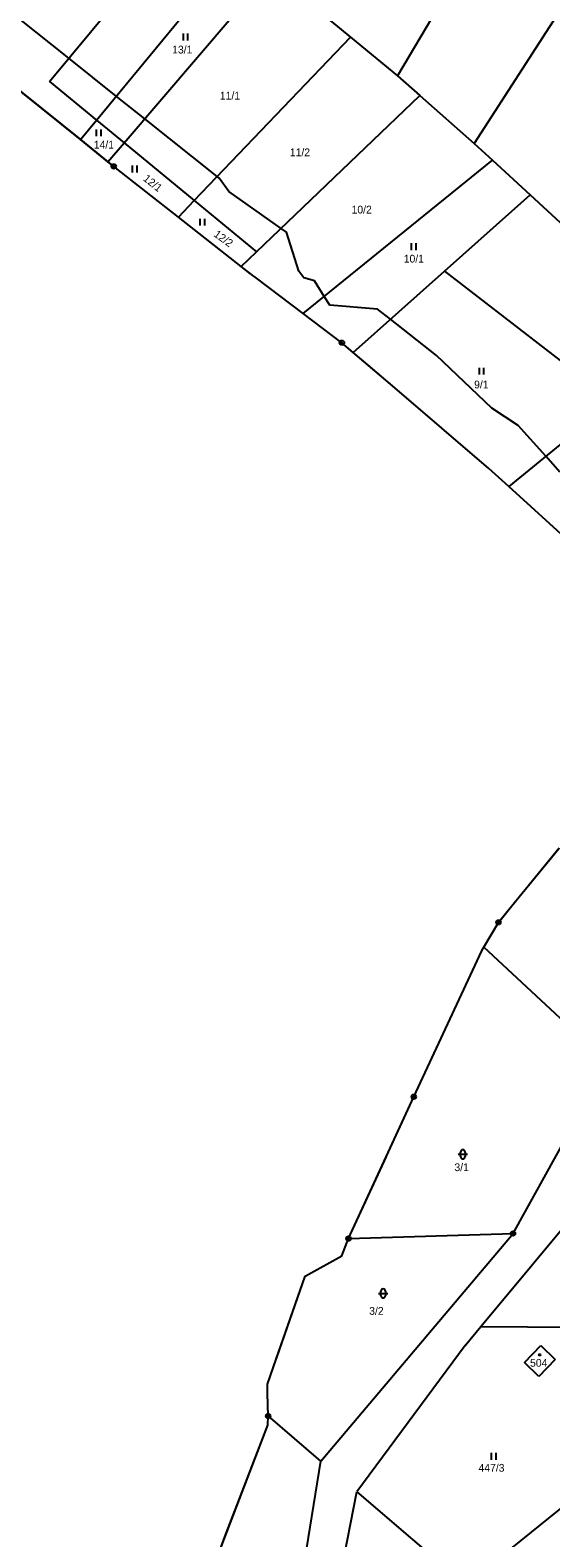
# Model space of a CAD drawing. Extents: x -445050 to -440454, y -1134563 to -1129741.
# Drawn here: x -443020.5 to -442906.4, y -1131200.4 to -1130870 of the extents above; entities that cross this region are included whole.
import ezdxf

# ---------------------------------------------------------------- set-up
doc = ezdxf.new("R2010")
doc.units = 0
for name, color, linetype in [('Vrstva 1', 7, 'Continuous'), ('Vrstva 13', 7, 'Continuous'), ('Vrstva 18', 7, 'Continuous'), ('Vrstva 19', 7, 'Continuous'), ('Vrstva 24', 7, 'Continuous'), ('Vrstva 25', 7, 'Continuous'), ('Vrstva 3', 7, 'Continuous'), ('Vrstva 37', 7, 'Continuous'), ('Vrstva 52', 7, 'Continuous')]:
    doc.layers.add(name, color=color, linetype=linetype)

msp = doc.modelspace()

# ---------------------------------------------------------------- linework, layer by layer
at = {"layer": 'Vrstva 1'}
for p, q in [((-442921.71, -1131154.07), (-442895.21, -1131122.14)), ((-442950.71, -1131134.82), (-442914.67, -1131133.71)), ((-442925.19, -1131158.26), (-442921.71, -1131154.07)), ((-442921.71, -1131154.07), (-442901.29, -1131154.25))]:
    msp.add_line(p, q, dxfattribs=at)
for points in [[(-442886.95, -1130790.6), (-442940, -1130880.07)], [(-442864.79, -1130804.31), (-442923.19, -1130894.89)], [(-443016.25, -1130881.25), (-442984.58, -1130843.19)], [(-443005.94, -1130889.74), (-442974.45, -1130851.57)], [(-442999.88, -1130894.74), (-442967.75, -1130857.11)], [(-442962.01, -1130861.86), (-442950.31, -1130871.54)], [(-442984.54, -1130907.39), (-442950.31, -1130871.54)], [(-442950.31, -1130871.54), (-442940, -1130880.07)], [(-443016.25, -1130881.25), (-443005.94, -1130889.74)], [(-442940, -1130880.07), (-442935.12, -1130884.38)], [(-442970.89, -1130918.64), (-442935.12, -1130884.38)], [(-442935.12, -1130884.38), (-442923.19, -1130894.89)], [(-443009.46, -1130894.01), (-443005.94, -1130889.74)], [(-443005.94, -1130889.74), (-442999.88, -1130894.74)], [(-443003.41, -1130898.87), (-442999.88, -1130894.74)], [(-442999.88, -1130894.74), (-442984.54, -1130907.39)], [(-442923.19, -1130894.89), (-442919.18, -1130898.55)], [(-442960.65, -1130932.13), (-442919.18, -1130898.55)], [(-442919.18, -1130898.55), (-442910.91, -1130906.11)], [(-442988, -1130911.01), (-442984.54, -1130907.39)], [(-442984.54, -1130907.39), (-442970.89, -1130918.64)], [(-442929.68, -1130922.83), (-442910.91, -1130906.11)], [(-442910.91, -1130906.11), (-442904.31, -1130912.16)], [(-442974.22, -1130921.83), (-442970.89, -1130918.64)], [(-442949.68, -1130940.64), (-442929.68, -1130922.83)], [(-442929.68, -1130922.83), (-442892.79, -1130951.31)], [(-442903.63, -1130960.22), (-442915.59, -1130970.05)], [(-442893.88, -1131096.24), (-442921.05, -1131070.95)], [(-442914.67, -1131133.71), (-442893.88, -1131096.24)], [(-442956.76, -1131183.61), (-442914.67, -1131133.71)], [(-442925.19, -1131158.26), (-442948.92, -1131190.32)], [(-442912.17, -1131161.94), (-442908.6, -1131158.27)], [(-442908.6, -1131158.27), (-442905.43, -1131161.35)], [(-442909, -1131165.02), (-442912.17, -1131161.94)], [(-442905.43, -1131161.35), (-442909, -1131165.02)], [(-442956.76, -1131183.61), (-442968.32, -1131173.69)], [(-442925.04, -1131210.79), (-442888.24, -1131181.08)], [(-442963.39, -1131224.72), (-442956.76, -1131183.61)], [(-442955.74, -1131225.39), (-442948.92, -1131190.32)], [(-442948.92, -1131190.32), (-442925.04, -1131210.79)]]:
    msp.add_lwpolyline(points, dxfattribs=at)
at = {"layer": 'Vrstva 13'}
for points in [[(-443030.66, -1130876.94), (-443009.46, -1130894.01)], [(-443009.46, -1130894.01), (-443003.41, -1130898.87)], [(-443003.41, -1130898.87), (-443002.15, -1130899.89)], [(-442988, -1130911.01), (-443002.15, -1130899.89)], [(-442974.22, -1130921.83), (-442988, -1130911.01)], [(-442971.95, -1130923.61), (-442974.22, -1130921.83)], [(-442970.89, -1130924.41), (-442971.95, -1130923.61)], [(-442960.65, -1130932.13), (-442970.89, -1130924.41)], [(-442952.16, -1130938.52), (-442960.65, -1130932.13)], [(-442949.68, -1130940.64), (-442952.16, -1130938.52)], [(-442940.07, -1130948.87), (-442949.68, -1130940.64)], [(-442919.98, -1130966.06), (-442940.07, -1130948.87)], [(-442915.59, -1130970.05), (-442919.98, -1130966.06)], [(-442899.33, -1130984.82), (-442915.59, -1130970.05)], [(-442904.54, -1131049.3), (-442917.86, -1131065.53)], [(-442921.05, -1131070.95), (-442917.86, -1131065.53)], [(-442936.4, -1131103.74), (-442921.53, -1131071.78)], [(-442921.53, -1131071.78), (-442921.05, -1131070.95)], [(-442950.71, -1131134.82), (-442936.4, -1131103.74)], [(-442952.18, -1131138.59), (-442950.71, -1131134.82)], [(-442960.2, -1131143.04), (-442952.18, -1131138.59)], [(-442966.56, -1131161.26), (-442960.2, -1131143.04)], [(-442968.46, -1131166.69), (-442966.56, -1131161.26)], [(-442968.47, -1131168.76), (-442968.46, -1131166.69)], [(-442968.32, -1131173.69), (-442968.47, -1131168.76)], [(-442977.78, -1131200.15), (-442968.4, -1131175.73)], [(-442968.4, -1131175.73), (-442968.32, -1131173.69)], [(-442978.94, -1131203.16), (-442977.78, -1131200.15)]]:
    msp.add_lwpolyline(points, dxfattribs=at)
at = {"layer": 'Vrstva 24'}
for centre, radius in [((-443002.15, -1130899.89), 0.5), ((-443002.15, -1130899.89), 0.1), ((-442952.16, -1130938.52), 0.5), ((-442952.16, -1130938.52), 0.1), ((-442917.86, -1131065.53), 0.5), ((-442917.86, -1131065.53), 0.1), ((-442936.4, -1131103.74), 0.5), ((-442936.4, -1131103.74), 0.1), ((-442950.71, -1131134.82), 0.5), ((-442950.71, -1131134.82), 0.1), ((-442914.67, -1131133.71), 0.5), ((-442914.67, -1131133.71), 0.1), ((-442968.32, -1131173.69), 0.5), ((-442968.32, -1131173.69), 0.1)]:
    msp.add_circle(centre, radius, dxfattribs=at)
at = {"layer": 'Vrstva 25'}
for p, q in [((-442986.9, -1130872.27), (-442986.9, -1130870.77)), ((-442985.9, -1130872.27), (-442985.9, -1130870.77)), ((-443005.94, -1130893.3), (-443005.94, -1130891.8)), ((-443004.94, -1130893.3), (-443004.94, -1130891.8)), ((-442998.01, -1130901.2), (-442998.01, -1130899.7)), ((-442997.01, -1130901.2), (-442997.01, -1130899.7)), ((-442983.21, -1130912.87), (-442983.21, -1130911.37)), ((-442982.21, -1130912.87), (-442982.21, -1130911.37)), ((-442936.89, -1130918.21), (-442936.89, -1130916.71)), ((-442935.89, -1130918.21), (-442935.89, -1130916.71)), ((-442922.04, -1130945.49), (-442922.04, -1130943.99)), ((-442921.04, -1130945.49), (-442921.04, -1130943.99)), ((-442926.16, -1131116.85), (-442926.16, -1131115.85)), ((-442925.16, -1131115.85), (-442925.16, -1131116.85)), ((-442926.66, -1131116.35), (-442924.66, -1131116.35)), ((-442944.13, -1131146.84), (-442942.13, -1131146.84)), ((-442943.63, -1131147.34), (-442943.63, -1131146.34)), ((-442942.63, -1131146.34), (-442942.63, -1131147.34)), ((-442919.39, -1131183.3), (-442919.39, -1131181.8)), ((-442918.39, -1131183.3), (-442918.39, -1131181.8))]:
    msp.add_line(p, q, dxfattribs=at)
msp.add_circle((-442908.82, -1131160.3), 0.175, dxfattribs=at)
for centre, start, end in [((-442925.66, -1131115.85), 0, 180), ((-442925.66, -1131116.85), 180, 0), ((-442943.13, -1131146.34), 0, 180), ((-442943.13, -1131147.34), 180, 0)]:
    msp.add_arc(centre, 0.5, start, end, dxfattribs=at)
at = {"layer": 'Vrstva 3'}
for points in [[(-442912.17, -1131161.94), (-442908.6, -1131158.27)], [(-442908.6, -1131158.27), (-442905.43, -1131161.35)], [(-442909, -1131165.02), (-442912.17, -1131161.94)], [(-442905.43, -1131161.35), (-442909, -1131165.02)]]:
    msp.add_lwpolyline(points, dxfattribs=at)
at = {"layer": 'Vrstva 37'}
msp.add_circle((-442908.82, -1131160.3), 0.175, dxfattribs=at)
at = {"layer": 'Vrstva 52'}
for points in [[(-442904.42, -1130966.86), (-442907.51, -1130963.41), (-442913.56, -1130956.65), (-442919.3, -1130952.83), (-442931.42, -1130941.35), (-442941.53, -1130933.39), (-442944.38, -1130931.14), (-442954.8, -1130930.29), (-442956.02, -1130928.38), (-442958.2, -1130924.98), (-442960.54, -1130924.34), (-442961.6, -1130922.85), (-442964.3, -1130914.3), (-442965.49, -1130913.47), (-442976.91, -1130905.42), (-442979.03, -1130902.44), (-442979.48, -1130902.09), (-442995.36, -1130889.44), (-443001.59, -1130884.47), (-443012.02, -1130876.17), (-443022.73, -1130867.63)], [(-442882.23, -1131001.82), (-442891.39, -1130992.04), (-442895.35, -1130988.44), (-442899.33, -1130984.82), (-442906.63, -1130978.19), (-442915.59, -1130970.05), (-442919.98, -1130966.06), (-442940.07, -1130948.87), (-442946.49, -1130943.37), (-442949.68, -1130940.64), (-442952.16, -1130938.52), (-442960.65, -1130932.13), (-442970.89, -1130924.41), (-442971.95, -1130923.61), (-442972.2, -1130923.41), (-442974.22, -1130921.83), (-442988, -1130911.01), (-443002.15, -1130899.89), (-443003.41, -1130898.87), (-443009.46, -1130894.01), (-443030.66, -1130876.94)], [(-442978.94, -1131203.16), (-442968.4, -1131175.73), (-442968.32, -1131173.69), (-442968.47, -1131168.76), (-442968.46, -1131166.69), (-442966.56, -1131161.26), (-442966.43, -1131160.87), (-442960.2, -1131143.04), (-442952.18, -1131138.59), (-442950.71, -1131134.82), (-442942.42, -1131116.8), (-442942.39, -1131116.76), (-442936.4, -1131103.74), (-442921.53, -1131071.78), (-442921.33, -1131071.43), (-442921.05, -1131070.95), (-442917.86, -1131065.53), (-442914.32, -1131061.21), (-442904.54, -1131049.3)]]:
    msp.add_lwpolyline(points, dxfattribs=at)

# ---------------------------------------------------------------- texts
at = {"layer": 'Vrstva 18'}
for s, p in [('13/1', (-442989.35, -1130875.15)), ('11/1', (-442978.9, -1130885.24)), ('14/1', (-443006.52, -1130895.98)), ('11/2', (-442963.56, -1130897.65)), ('10/2', (-442950.04, -1130910.21)), ('10/1', (-442938.61, -1130920.96)), ('9/1', (-442923.2, -1130948.53)), ('3/1', (-442927.51, -1131120.04)), ('3/2', (-442946.18, -1131151.52)), ('447/3', (-442922.23, -1131185.9))]:
    msp.add_text(s, height=1.7, dxfattribs=at).set_placement(p)
for s, rotation, p in [('12/1', 321.4326, (-442995.86, -1130902.83)), ('12/2', 324.0925, (-442980.4, -1130915.08))]:
    msp.add_text(s, height=1.7, rotation=rotation, dxfattribs=at).set_placement(p)
at = {"layer": 'Vrstva 19'}
msp.add_text('504', height=1.7, dxfattribs=at).set_placement((-442910.94, -1131162.9))

doc.saveas('drawing.dxf')
